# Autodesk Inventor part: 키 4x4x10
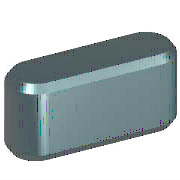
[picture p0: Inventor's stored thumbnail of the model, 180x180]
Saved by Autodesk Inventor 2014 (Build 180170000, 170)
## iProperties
IsCustomPart: 1
Created: 2012-02
Part Number: 키 4x4x10
Material: 강철, 연강
Description: 키 및 해당 키홈
Document SubType Name: Modeling
Standard: KS B 1311
Designer: test
Standards Organization: KS
Language: ko-KR
Size Designation: 4 x 4 x 10
Categories: <MemberInstance><Categories><Category DisplayName="샤프트 부품" InternalName="7f7aeb1f-a693-4053-b835-cee3144e0d98" Mnemonic="SHFT"><Category DisplayName="키" Interna
Density: 1 g/cm^3
Appearance: 노란색
Author: test
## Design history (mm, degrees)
workplane "Work Plane1"
workplane "Work Plane2"
sketch "스케치1"
  geometry: L1 (2, 2)-(8, 2); L2 (8, -2)-(2, -2); L3 (0, 9.4)-(0, -7.4) reference; L4 (-5, 0)-(30, 0) reference; L5 (10, 0)-(10, 7); A1 r 2 centre (2, 0) between (2, 2) and (2, -2); A2 r 2 centre (8, 0) between (8, -2) and (8, 2)
  constraints: 6 end point, 5 point on circle, 4 tangent, 3 point on line, 2 centre point, 1 horizontal, 1 parallel, 1 perpendicular
  dimensions: "d0" = 2 radius of A1 (= 0.5 x PB); "d13" = 2 radius of A2 (= 0.5 x PB); "d14" = 10 distance between parallel lines of L5 L3 (= NLG)
extrude "본체1" new body sketch "스케치1" taper "d3" = 0 deg; stored distance "d4" = 10
workplane "Work Plane3"
body "Solid1"
chamfer "모따기1" distance "d8" = 0.25 (= PHH); stored, may be unused: second distance "d9" = 0.25 (= PHH), angle "d15" = 45 deg
other parameters: "d1" = -2.5 (= -PNT), "d2" = 1.5 (= PH - PNT), "NLG" = 10 [user parameter; used in 3 equation terms], "PB" = 4 [user parameter; used in 2 equation terms], "PNT" = 2.5 [user parameter; used in 2 equation terms], "PH" = 4 [user parameter; used in 1 equation term], "PHH" = 0.25 [user parameter; used in 2 equation terms], "d10" = 0, "d16" = 0, "d17" = 0, "d18" = 0, "WDMAX" = 12 [user parameter], "RR" = 0.08 [user parameter], "PUEB" = 1.8 [user parameter]
